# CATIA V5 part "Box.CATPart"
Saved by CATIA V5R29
Part number: Box
Source: Unknown
Bounding box of the stored display mesh (mm): x -90 to 90, y -135 to 135, z 0 to 150
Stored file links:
  C:\가치같이\SmartFactory_BoxErectorConveyor\Boxing(over)\Box.CATPart
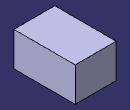
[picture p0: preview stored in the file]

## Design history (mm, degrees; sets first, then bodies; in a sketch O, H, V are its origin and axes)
Body1 (main body)
  Solid1 "PartBody": solid without history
